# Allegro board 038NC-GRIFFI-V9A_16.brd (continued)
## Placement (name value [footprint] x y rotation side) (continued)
NOREF#1212  -  []  36 240.62 90 top
NOREF#1213  -  []  238.35 207.84 315 top
NOREF#1214  -  []  147.36 268.69 0 top
NOREF#1215  -  []  87.32 457.2 0 top
NOREF#1216  -  []  199.67 181.33 90 top
NOREF#1217  -  []  60.19 265.47 90 top
NOREF#1218  -  []  74.99 283.99 0 top
NOREF#1219  -  []  136.47 229.18 90 top
NOREF#1220  -  []  196.47 301.68 90 top
NOREF#1221  -  []  225.06 203.86 0 top
NOREF#1222  -  []  60.84 300.88 90 top
NOREF#1223  -  []  115.97 164.05 90 top
NOREF#1224  -  []  224.98 281.49 90 top
NOREF#1225  -  []  105.92 225.18 90 top
NOREF#1226  -  []  175.7 198.99 90 top
NOREF#1227  -  []  43.9 20.69 90 top
NOREF#1228  -  []  91.47 105.11 90 top
NOREF#1229  -  []  134.98 193.49 90 top
NOREF#1230  -  []  207.95 83.81 0 top
NOREF#1231  -  []  30.19 205.47 90 top
NOREF#1232  -  []  78.48 174.1 0 top
NOREF#1233  -  []  104.99 281.49 90 top
NOREF#1234  -  []  16.47 301.68 0 top
NOREF#1235  -  []  44.4 120.65 0 top
NOREF#1236  -  []  153.41 234.38 0 top
NOREF#1237  -  []  113.38 284.14 90 top
NOREF#1238  -  []  58.45 115.65 90 top
NOREF#1239  -  []  75.92 300.88 90 top
NOREF#1240  -  []  98.86 233.58 0 top
NOREF#1241  -  []  232.98 226.49 0 top
NOREF#1242  -  []  158.86 139.12 90 top
NOREF#1243  -  []  194.3 17.15 90 top
NOREF#1244  -  []  82.73 114.89 0 top
NOREF#1245  -  []  60.19 205.86 90 top
NOREF#1246  -  []  27.13 170.1 90 top
NOREF#1247  -  []  226.47 304.88 90 top
NOREF#1248  -  []  177.17 105.04 0 top
NOREF#1249  -  []  45.06 269.26 90 top
NOREF#1250  -  []  143.93 290.34 90 top
NOREF#1251  -  []  83.93 231.38 90 top
NOREF#1252  -  []  31.01 206.29 90 top
NOREF#1253  -  []  136.47 225.98 90 top
NOREF#1254  -  []  160.89 283.29 90 top
NOREF#1255  -  []  22.99 286.49 0 top
NOREF#1256  -  []  64.59 287.14 90 top
NOREF#1257  -  []  55.97 179.68 90 top
NOREF#1258  -  []  172.98 188.49 90 top
NOREF#1259  -  []  135.92 284.14 90 top
NOREF#1260  -  []  31.01 206.69 90 top
NOREF#1261  -  []  154.59 230.38 90 top
NOREF#1262  -  []  124.59 230.38 90 top
NOREF#1263  -  []  154.59 289.34 90 top
NOREF#1264  -  []  139.67 183.53 90 top
NOREF#1265  -  []  91.4 292.54 0 top
NOREF#1266  -  []  106.47 249.87 0 top
NOREF#1267  -  []  57.13 303.88 90 top
NOREF#1268  -  []  98.86 142.32 90 top
NOREF#1269  -  []  91.4 307.08 90 top
NOREF#1270  -  []  98.86 301.68 90 top
NOREF#1271  -  []  22.99 248.49 0 top
NOREF#1272  -  []  244.59 225.98 90 top
NOREF#1273  -  []  104.99 193.49 90 top
NOREF#1274  -  []  137.98 278.49 0 top
NOREF#1275  -  []  221.4 296.54 90 top
NOREF#1276  -  []  75.06 209.26 90 top
NOREF#1277  -  []  28.78 456.29 0 top
NOREF#1278  -  []  222.48 284.14 0 top
NOREF#1279  -  []  166.47 301.68 90 top
NOREF#1280  -  []  35.02 225.18 0 top
NOREF#1281  -  []  63.41 293.34 0 top
NOREF#1282  -  []  30 300.03 0 top
NOREF#1283  -  []  60.34 266.14 90 top
NOREF#1284  -  []  134.98 283.99 0 top
NOREF#1285  -  []  162.06 244.47 90 top
NOREF#1286  -  []  211.39 168.9 90 top
NOREF#1287  -  []  236.96 268.69 0 top
NOREF#1288  -  []  94.59 287.14 90 top
NOREF#1289  -  []  31.4 307.08 90 top
NOREF#1290  -  []  37.36 333.84 90 top
NOREF#1291  -  []  184.59 287.14 90 top
NOREF#1292  -  []  15.07 300.03 0 top
NOREF#1293  -  []  68.31 300.88 90 top
NOREF#1294  -  []  94.59 289.34 90 top
NOREF#1295  -  []  57.36 208.69 0 top
NOREF#1296  -  []  218.86 139.12 0 top
NOREF#1297  -  []  117.79 269.51 0 top
NOREF#1298  -  []  48.48 174.1 0 top
NOREF#1299  -  []  235.94 234.38 0 top
NOREF#1300  -  []  130.18 389.27 90 top
NOREF#1301  -  []  198.48 250.67 0 top
NOREF#1302  -  []  149.43 456.29 0 top
NOREF#1303  -  []  117.13 185.73 90 top
NOREF#1304  -  []  90.34 266.14 90 top
NOREF#1305  -  []  207.13 246.67 90 top
NOREF#1306  -  []  44.99 223.99 0 top
NOREF#1307  -  []  131.02 174.1 0 top
NOREF#1308  -  []  44.99 253.49 90 top
NOREF#1309  -  []  187.55 263.78 0 top
NOREF#1310  -  []  177.13 303.88 90 top
NOREF#1311  -  []  124.59 228.18 90 top
NOREF#1312  -  []  71.82 117.35 90 top
NOREF#1313  -  []  172.98 248.49 0 top
NOREF#1314  -  []  163.73 103.85 90 top
NOREF#1315  -  []  132.06 165.7 90 top
NOREF#1316  -  []  237.13 244.47 90 top
NOREF#1317  -  []  74.99 250.99 90 top
NOREF#1318  -  []  190.89 237.58 90 top
NOREF#1319  -  []  164.56 456.29 90 top
NOREF#1320  -  []  42.06 228.18 90 top
NOREF#1321  -  []  193.01 240.57 90 top
NOREF#1322  -  []  81.92 389.27 90 top
NOREF#1323  -  []  59.02 105.89 90 top
NOREF#1324  -  []  65.02 225.18 0 top
NOREF#1325  -  []  14.99 221.49 90 top
NOREF#1326  -  []  27.13 244.47 90 top
NOREF#1327  -  []  210.67 176.51 90 top
NOREF#1328  -  []  52.99 226.49 0 top
NOREF#1329  -  []  71.03 112.93 0 top
NOREF#1330  -  []  179.38 269.51 0 top
NOREF#1331  -  []  170.17 17.15 0 top
NOREF#1332  -  []  44.99 193.49 90 top
NOREF#1333  -  []  188.86 307.08 90 top
NOREF#1334  -  []  60.84 164.9 90 top
NOREF#1335  -  []  47.99 256.49 90 top
NOREF#1336  -  []  76.47 304.88 90 top
NOREF#1337  -  []  213.41 250.67 0 top
NOREF#1338  -  []  158.39 253.49 45 top
NOREF#1339  -  []  108.48 174.1 0 top
NOREF#1340  -  []  221.02 174.1 0 top
NOREF#1341  -  []  195.92 225.18 90 top
NOREF#1342  -  []  101.02 189.73 0 top
NOREF#1343  -  []  41.02 189.73 0 top
NOREF#1344  -  []  248.86 173.3 0 top
NOREF#1345  -  []  57.82 107.19 0 top
NOREF#1346  -  []  92.32 110.11 0 top
NOREF#1347  -  []  161.02 174.1 0 top
NOREF#1348  -  []  214.59 183.53 90 top
NOREF#1349  -  []  98.86 292.54 0 top
NOREF#1350  -  []  20.74 275.74 0 top
NOREF#1351  -  []  218.86 307.08 90 top
NOREF#1352  -  []  134.98 281.49 90 top
NOREF#1353  -  []  42.61 174.1 0 top
NOREF#1354  -  []  173.66 106.41 90 top
NOREF#1355  -  []  183.43 240.62 90 top
NOREF#1356  -  []  147.63 208.84 0 top
NOREF#1357  -  []  207.63 268.84 0 top
NOREF#1358  -  []  132.06 185.73 90 top
NOREF#1359  -  []  226.47 284.94 90 top
NOREF#1360  -  []  194.98 221.49 90 top
NOREF#1361  -  []  14.22 225.18 90 top
NOREF#1362  -  []  102.48 225.18 0 top
NOREF#1363  -  []  177.79 269.51 0 top
NOREF#1364  -  []  209.32 268.11 315 top
NOREF#1365  -  []  187.23 259.24 90 top
NOREF#1366  -  []  188.86 139.12 90 top
NOREF#1367  -  []  49.67 244.47 90 top
NOREF#1368  -  []  46.47 301.68 0 top
NOREF#1369  -  []  37.46 300.03 90 top
NOREF#1370  -  []  173.93 231.38 90 top
NOREF#1371  -  []  55.7 258.99 90 top
NOREF#1372  -  []  177.13 242.27 90 top
NOREF#1373  -  []  100.89 240.62 90 top
NOREF#1374  -  []  53.93 229.18 90 top
NOREF#1375  -  []  87.64 268.84 0 top
NOREF#1376  -  []  43.81 238.87 0 top
NOREF#1377  -  []  113.93 173.3 0 top
NOREF#1378  -  []  121.39 249.87 0 top
NOREF#1379  -  []  37.46 251.52 0 top
NOREF#1380  -  []  133.3 120.65 0 top
NOREF#1381  -  []  31.4 292.54 0 top
NOREF#1382  -  []  94.59 230.38 90 top
NOREF#1383  -  []  202.98 248.49 90 top
NOREF#1384  -  []  124.59 284.94 90 top
NOREF#1385  -  []  208.35 207.84 315 top
NOREF#1386  -  []  151.39 233.58 0 top
NOREF#1387  -  []  57.79 209.51 0 top
NOREF#1388  -  []  235.7 198.99 90 top
NOREF#1389  -  []  64.59 228.18 90 top
NOREF#1390  -  []  46.47 304.88 90 top
NOREF#1391  -  []  57.13 306.08 90 top
NOREF#1392  -  []  132.48 225.18 0 top
NOREF#1393  -  []  157.55 263.78 0 top
NOREF#1394  -  []  91.4 165.7 90 top
NOREF#1395  -  []  34.6 225.98 90 top
NOREF#1396  -  []  116.96 208.69 0 top
NOREF#1397  -  []  42.48 225.18 0 top
NOREF#1398  -  []  74.99 281.49 90 top
NOREF#1399  -  []  83.93 188.93 0 top
NOREF#1400  -  []  78.48 189.73 0 top
NOREF#1401  -  []  33.99 389.27 90 top
NOREF#1402  -  []  227.03 389.27 90 top
NOREF#1403  -  []  19.78 456.29 0 top
NOREF#1404  -  []  79.67 167.9 90 top
NOREF#1405  -  []  190.78 112.83 0 top
NOREF#1406  -  []  161.02 189.73 0 top
NOREF#1407  -  []  100.89 224.33 90 top
NOREF#1408  -  []  23.93 229.18 90 top
NOREF#1409  -  []  22.99 188.49 0 top
NOREF#1410  -  []  190.47 111.76 90 top
NOREF#1411  -  []  128.86 142.32 90 top
NOREF#1412  -  []  135.56 82.55 0 top
NOREF#1413  -  []  203.93 284.94 90 top
NOREF#1414  -  []  85.97 164.05 90 top
NOREF#1415  -  []  3.61 203.06 0 top
NOREF#1416  -  []  91.47 115.65 90 top
NOREF#1417  -  []  233.38 284.14 90 top
NOREF#1418  -  []  102.06 244.47 90 top
NOREF#1419  -  []  99.47 115.65 0 top
NOREF#1420  -  []  243.41 189.73 0 top
NOREF#1421  -  []  243.56 82.65 0 top
NOREF#1422  -  []  145.7 198.99 90 top
NOREF#1423  -  []  107.21 143.34 90 top
NOREF#1424  -  []  37.55 263.78 0 top
NOREF#1425  -  []  117.13 246.67 90 top
NOREF#1426  -  []  203.93 309.28 0 top
NOREF#1427  -  []  138.36 240.62 90 top
NOREF#1428  -  []  229.67 170.1 90 top
NOREF#1429  -  []  173.93 249.87 0 top
NOREF#1430  -  []  135.92 300.88 90 top
NOREF#1431  -  []  17.53 452.29 90 top
NOREF#1432  -  []  178.37 267.15 315 top
NOREF#1433  -  []  55.7 198.99 90 top
NOREF#1434  -  []  93.43 300.03 90 top
NOREF#1435  -  []  230.48 210.77 0 top
NOREF#1436  -  []  104.99 223.99 0 top
NOREF#1437  -  []  192.06 287.14 90 top
NOREF#1438  -  []  258.36 179.68 90 top
NOREF#1439  -  []  199.93 18.69 90 top
NOREF#1440  -  []  108.48 189.73 0 top
NOREF#1441  -  []  36 283.29 90 top
NOREF#1442  -  []  101.4 296.54 90 top
NOREF#1443  -  []  207.36 268.69 0 top
NOREF#1444  -  []  169.67 332.66 90 top
NOREF#1445  -  []  211.39 301.68 0 top
NOREF#1446  -  []  130.89 283.29 90 top
NOREF#1447  -  []  87.36 208.69 0 top
NOREF#1448  -  []  86.96 268.69 0 top
NOREF#1449  -  []  221.02 189.73 0 top
NOREF#1450  -  []  244.59 230.38 90 top
NOREF#1451  -  []  151.39 168.9 90 top
NOREF#1452  -  []  28.37 207.15 315 top
NOREF#1453  -  []  45.92 300.88 90 top
NOREF#1454  -  []  149.39 269.51 0 top
NOREF#1455  -  []  143.93 249.87 0 top
NOREF#1456  -  []  227.98 196.49 90 top
NOREF#1457  -  []  188.69 396.29 0 top
NOREF#1458  -  []  31.02 18.69 90 top
NOREF#1459  -  []  121.91 17.2 0 top
NOREF#1460  -  []  196.47 231.38 90 top
NOREF#1461  -  []  70.89 283.29 90 top
NOREF#1462  -  []  52.99 248.49 0 top
NOREF#1463  -  []  57.13 183.53 90 top
NOREF#1464  -  []  136.47 284.94 90 top
NOREF#1465  -  []  211.39 233.58 0 top
NOREF#1466  -  []  38.66 177.76 90 top
NOREF#1467  -  []  194.98 223.99 0 top
NOREF#1468  -  []  138.36 164.05 90 top
NOREF#1469  -  []  124.59 225.98 90 top
NOREF#1470  -  []  106.47 284.94 0 top
NOREF#1471  -  []  181.39 304.88 90 top
NOREF#1472  -  []  191.4 296.54 90 top
NOREF#1473  -  []  157.36 333.84 90 top
NOREF#1474  -  []  117.13 244.47 90 top
NOREF#1475  -  []  173.93 284.94 0 top
NOREF#1476  -  []  154.59 246.67 90 top
NOREF#1477  -  []  169.67 181.33 90 top
NOREF#1478  -  []  227.21 143.34 90 top
NOREF#1479  -  []  14.99 250.99 90 top
NOREF#1480  -  []  94.22 115.65 0 top
NOREF#1481  -  []  117.13 183.53 90 top
NOREF#1482  -  []  136.47 284.94 0 top
NOREF#1483  -  []  157.55 203.78 0 top
NOREF#1484  -  []  230.73 215.74 0 top
NOREF#1485  -  []  22.53 283.29 0 top
NOREF#1486  -  []  205.7 198.99 90 top
NOREF#1487  -  []  27.13 165.7 90 top
NOREF#1488  -  []  44.99 281.49 90 top
NOREF#1489  -  []  61.01 206.69 90 top
NOREF#1490  -  []  89.39 269.51 0 top
NOREF#1491  -  []  188.86 173.3 0 top
NOREF#1492  -  []  120.34 266.14 90 top
NOREF#1493  -  []  213.41 234.38 0 top
NOREF#1494  -  []  127.41 115.65 0 top
NOREF#1495  -  []  23.93 225.98 90 top
NOREF#1496  -  []  63.43 240.62 90 top
NOREF#1497  -  []  83.93 225.98 0 top
NOREF#1498  -  []  14.99 190.99 90 top
NOREF#1499  -  []  115.7 198.99 90 top
NOREF#1500  -  []  46.47 225.98 0 top
NOREF#1501  -  []  210.33 206.14 90 top
NOREF#1502  -  []  228.48 310.08 0 top
NOREF#1503  -  []  230.48 270.77 0 top
NOREF#1504  -  []  43.88 117.35 90 top
NOREF#1505  -  []  89.32 208.11 315 top
NOREF#1506  -  []  140.43 456.29 0 top
NOREF#1507  -  []  27.13 167.9 90 top
NOREF#1508  -  []  196.47 229.18 90 top
NOREF#1509  -  []  115.97 326.61 90 top
NOREF#1510  -  []  248.86 301.68 90 top
NOREF#1511  -  []  207.13 301.68 90 top
NOREF#1512  -  []  211.68 19.69 90 top
NOREF#1513  -  []  219.43 82.65 0 top
NOREF#1514  -  []  29.32 268.11 315 top
NOREF#1515  -  []  150.18 265.47 90 top
NOREF#1516  -  []  23.93 231.38 90 top
NOREF#1517  -  []  222.06 284.94 90 top
NOREF#1518  -  []  177.13 246.67 90 top
NOREF#1519  -  []  224.98 190.99 90 top
NOREF#1520  -  []  252.06 246.67 90 top
NOREF#1521  -  []  177.41 138.32 0 top
NOREF#1522  -  []  218.86 301.68 90 top
NOREF#1523  -  []  59.02 106.54 90 top
NOREF#1524  -  []  43.88 106.81 0 top
NOREF#1525  -  []  97.36 333.84 90 top
NOREF#1526  -  []  44.99 221.49 90 top
NOREF#1527  -  []  198.48 189.73 0 top
NOREF#1528  -  []  92.16 18.69 0 top
NOREF#1529  -  []  158.86 173.3 0 top
NOREF#1530  -  []  191.02 189.73 0 top
NOREF#1531  -  []  222.48 225.18 0 top
NOREF#1532  -  []  30.19 265.86 90 top
NOREF#1533  -  []  242.56 17.15 90 top
NOREF#1534  -  []  217.23 259.24 90 top
NOREF#1535  -  []  106.47 225.98 90 top
NOREF#1536  -  []  147.13 306.08 90 top
NOREF#1537  -  []  243.43 240.62 90 top
NOREF#1538  -  []  136.47 307.08 90 top
NOREF#1539  -  []  30 294.19 0 top
NOREF#1540  -  []  15.07 300.03 90 top
NOREF#1541  -  []  122.91 82.65 0 top
NOREF#1542  -  []  104.99 190.99 90 top
NOREF#1543  -  []  113.93 229.18 90 top
NOREF#1544  -  []  91.4 165.7 0 top
NOREF#1545  -  []  154.59 185.73 90 top
NOREF#1546  -  []  218.86 233.58 0 top
NOREF#1547  -  []  16.47 307.08 90 top
NOREF#1548  -  []  215.02 284.14 0 top
NOREF#1549  -  []  142.98 226.49 0 top
NOREF#1550  -  []  198.48 310.08 0 top
NOREF#1551  -  []  233.93 288.14 90 top
NOREF#1552  -  []  241.01 206.69 90 top
NOREF#1553  -  []  68.86 144.52 90 top
NOREF#1554  -  []  145.94 250.67 0 top
NOREF#1555  -  []  238.65 206.87 45 top
NOREF#1556  -  []  102.06 284.94 90 top
NOREF#1557  -  []  59.32 268.11 315 top
NOREF#1558  -  []  206.96 268.69 0 top
NOREF#1559  -  []  162.06 181.33 90 top
NOREF#1560  -  []  42.06 244.47 90 top
NOREF#1561  -  []  213.41 189.73 0 top
NOREF#1562  -  []  211.39 301.68 90 top
NOREF#1563  -  []  169.67 183.53 90 top
NOREF#1564  -  []  127.55 454.29 90 top
NOREF#1565  -  []  225.92 300.88 90 top
NOREF#1566  -  []  38.86 307.08 90 top
NOREF#1567  -  []  124.59 287.14 90 top
NOREF#1568  -  []  74.99 221.49 90 top
NOREF#1569  -  []  46.47 173.3 0 top
NOREF#1570  -  []  61.01 266.69 90 top
NOREF#1571  -  []  113.93 188.93 0 top
NOREF#1572  -  []  57.41 138.32 0 top
NOREF#1573  -  []  145.97 179.68 90 top
NOREF#1574  -  []  85.97 179.68 90 top
NOREF#1575  -  []  180.33 206.14 90 top
NOREF#1576  -  []  20.49 210.77 0 top
NOREF#1577  -  []  27.36 268.69 0 top
NOREF#1578  -  []  207.13 306.08 90 top
NOREF#1579  -  []  188.86 139.12 0 top
NOREF#1580  -  []  55.97 164.05 90 top
NOREF#1581  -  []  211.39 304.88 90 top
NOREF#1582  -  []  250.89 179.68 90 top
NOREF#1583  -  []  166.47 249.87 0 top
NOREF#1584  -  []  208.37 207.15 315 top
NOREF#1585  -  []  95.02 284.14 0 top
NOREF#1586  -  []  100.9 237.58 90 top
NOREF#1587  -  []  162.06 246.67 90 top
NOREF#1588  -  []  58.37 207.15 315 top
NOREF#1589  -  []  26.96 208.69 0 top
NOREF#1590  -  []  121.39 292.54 0 top
NOREF#1591  -  []  211.01 206.29 90 top
NOREF#1592  -  []  67.24 199.24 90 top
NOREF#1593  -  []  253.01 240.57 90 top
NOREF#1594  -  []  33.43 179.68 90 top
NOREF#1595  -  []  79.29 454.29 90 top
NOREF#1596  -  []  15.06 203.86 90 top
NOREF#1597  -  []  211.01 206.69 90 top
NOREF#1598  -  []  130.89 240.62 90 top
NOREF#1599  -  []  57.36 268.69 0 top
NOREF#1600  -  []  74.99 193.49 90 top
NOREF#1601  -  []  77.99 218.49 0 top
NOREF#1602  -  []  123.43 179.68 90 top
NOREF#1603  -  []  74.99 221.49 90 top
NOREF#1604  -  []  158.31 300.88 90 top
NOREF#1605  -  []  224.98 283.99 0 top
NOREF#1606  -  []  39.06 458.49 0 top
NOREF#1607  -  []  180.84 164.9 90 top
NOREF#1608  -  []  139.67 332.66 90 top
NOREF#1609  -  []  87.13 181.33 90 top
NOREF#1610  -  []  130.9 239.1 90 top
NOREF#1611  -  []  55.97 240.62 90 top
NOREF#1612  -  []  136.47 335.86 0 top
NOREF#1613  -  []  48.48 250.67 0 top
NOREF#1614  -  []  239.38 269.51 0 top
NOREF#1615  -  []  178.65 266.87 45 top
NOREF#1616  -  []  63.61 203.06 0 top
NOREF#1617  -  []  16.47 225.98 0 top
NOREF#1618  -  []  151.39 188.93 0 top
NOREF#1619  -  []  72.06 287.14 90 top
NOREF#1620  -  []  178.35 207.84 315 top
NOREF#1621  -  []  125.02 300.88 0 top
NOREF#1622  -  []  38.86 139.12 0 top
NOREF#1623  -  []  50.52 82.65 0 top
NOREF#1624  -  []  154.59 287.14 90 top
NOREF#1625  -  []  61.01 206.29 90 top
NOREF#1626  -  []  97.24 199.24 90 top
NOREF#1627  -  []  237.41 138.32 0 top
NOREF#1628  -  []  16.47 225.98 90 top
NOREF#1629  -  []  89.29 207.51 45 top
NOREF#1630  -  []  190.78 112.83 90 top
NOREF#1631  -  []  49.67 165.7 90 top
NOREF#1632  -  []  37.55 203.78 0 top
NOREF#1633  -  []  38.51 115.65 0 top
NOREF#1634  -  []  146.03 119.76 0 top
NOREF#1635  -  []  106.47 301.68 90 top
NOREF#1636  -  []  240.65 236.45 90 top
NOREF#1637  -  []  237.13 185.73 90 top
NOREF#1638  -  []  117.13 181.33 90 top
NOREF#1639  -  []  59.02 107.84 90 top
NOREF#1640  -  []  148.35 267.84 315 top
NOREF#1641  -  []  238.35 207.84 45 top
NOREF#1642  -  []  233.38 225.18 90 top
NOREF#1643  -  []  151.39 307.08 90 top
NOREF#1644  -  []  53.93 225.98 90 top
NOREF#1645  -  []  210.18 205.47 90 top
NOREF#1646  -  []  195.92 300.88 90 top
NOREF#1647  -  []  243.41 234.38 0 top
NOREF#1648  -  []  192.48 225.18 0 top
NOREF#1649  -  []  236.95 456.29 0 top
NOREF#1650  -  []  187.23 199.24 90 top
NOREF#1651  -  []  136.47 301.68 0 top
NOREF#1652  -  []  214.59 287.14 90 top
NOREF#1653  -  []  146.96 208.69 0 top
NOREF#1654  -  []  199.67 183.53 90 top
NOREF#1655  -  []  128.73 111.38 90 top
NOREF#1656  -  []  150.18 265.86 90 top
NOREF#1657  -  []  205.97 164.05 90 top
NOREF#1658  -  []  88.35 267.84 45 top
NOREF#1659  -  []  145.94 234.38 0 top
NOREF#1660  -  []  181.01 206.69 90 top
NOREF#1661  -  []  94.59 284.94 90 top
NOREF#1662  -  []  49.67 181.33 90 top
NOREF#1663  -  []  244.59 284.94 90 top
NOREF#1664  -  []  53.93 284.94 0 top
NOREF#1665  -  []  240.18 205.86 90 top
NOREF#1666  -  []  90.65 236.45 90 top
NOREF#1667  -  []  205.97 326.61 90 top
NOREF#1668  -  []  61.4 304.88 90 top
NOREF#1669  -  []  123.41 293.34 0 top
NOREF#1670  -  []  130.9 237.58 90 top
NOREF#1671  -  []  224.98 253.49 90 top
NOREF#1672  -  []  91.4 304.88 90 top
NOREF#1673  -  []  135.06 267.06 90 top
NOREF#1674  -  []  74.99 223.99 0 top
NOREF#1675  -  []  44.99 190.99 90 top
NOREF#1676  -  []  38.86 139.12 90 top
NOREF#1677  -  []  146.04 17.15 0 top
NOREF#1678  -  []  198.48 174.1 0 top
NOREF#1679  -  []  199.67 242.27 90 top
NOREF#1680  -  []  14.99 281.49 90 top
NOREF#1681  -  []  105.06 263.86 90 top
NOREF#1682  -  []  230.73 275.74 0 top
NOREF#1683  -  []  207.13 167.9 90 top
NOREF#1684  -  []  194.98 221.49 90 top
NOREF#1685  -  []  42.06 242.27 90 top
NOREF#1686  -  []  241.01 266.69 90 top
NOREF#1687  -  []  98.86 307.08 90 top
NOREF#1688  -  []  37.46 294.19 0 top
NOREF#1689  -  []  169.94 300.88 0 top
NOREF#1690  -  []  67.36 333.84 90 top
NOREF#1691  -  []  147.79 269.51 0 top
NOREF#1692  -  []  115.97 240.62 90 top
NOREF#1693  -  []  243.41 250.67 0 top
NOREF#1694  -  []  128.86 173.3 0 top
NOREF#1695  -  []  42.61 234.38 0 top
NOREF#1696  -  []  98.86 139.12 0 top
NOREF#1697  -  []  252.06 228.18 90 top
NOREF#1698  -  []  34.6 289.34 90 top
NOREF#1699  -  []  169.94 164.9 0 top
NOREF#1700  -  []  38.39 253.49 45 top
NOREF#1701  -  []  87.79 269.51 0 top
NOREF#1702  -  []  177.79 209.51 0 top
NOREF#1703  -  []  179.38 209.51 0 top
NOREF#1704  -  []  237.13 306.08 90 top
NOREF#1705  -  []  229.67 165.7 90 top
NOREF#1706  -  []  81.68 112.1 0 top
NOREF#1707  -  []  252.06 181.33 90 top
NOREF#1708  -  []  102.06 246.67 90 top
NOREF#1709  -  []  154.31 14.59 90 top
NOREF#1710  -  []  252.06 185.73 90 top
NOREF#1711  -  []  130.49 14.59 90 top
NOREF#1712  -  []  58.65 266.87 45 top
NOREF#1713  -  []  169.67 185.73 90 top
NOREF#1714  -  []  45.06 263.86 90 top
NOREF#1715  -  []  164.98 281.49 90 top
NOREF#1716  -  []  147.13 170.1 90 top
NOREF#1717  -  []  112.99 248.49 0 top
NOREF#1718  -  []  78.36 179.68 90 top
NOREF#1719  -  []  170.48 270.77 0 top
NOREF#1720  -  []  196.47 307.08 90 top
NOREF#1721  -  []  105.36 120.65 0 top
NOREF#1722  -  []  14.99 193.49 90 top
NOREF#1723  -  []  78.36 240.62 90 top
NOREF#1724  -  []  76.47 284.94 0 top
NOREF#1725  -  []  85.7 198.99 90 top
NOREF#1726  -  []  97.78 17.2 90 top
NOREF#1727  -  []  188.86 233.58 0 top
NOREF#1728  -  []  94.59 244.47 90 top
NOREF#1729  -  []  161.4 298.06 90 top
NOREF#1730  -  []  38.86 144.52 90 top
NOREF#1731  -  []  16.47 301.68 90 top
NOREF#1732  -  []  142.98 248.49 0 top
NOREF#1733  -  []  125.3 456.29 0 top
NOREF#1734  -  []  188.86 144.52 90 top
NOREF#1735  -  []  178.44 389.27 90 top
NOREF#1736  -  []  81.95 109.2 90 top
NOREF#1737  -  []  68.86 307.08 90 top
NOREF#1738  -  []  14.22 225.18 0 top
NOREF#1739  -  []  88.37 207.15 315 top
NOREF#1740  -  []  150.65 236.45 90 top
NOREF#1741  -  []  164.98 193.49 90 top
NOREF#1742  -  []  134.98 221.49 90 top
NOREF#1743  -  []  220.89 179.68 90 top
NOREF#1744  -  []  52.99 188.49 0 top
NOREF#1745  -  []  224.98 221.49 90 top
NOREF#1746  -  []  115.88 237.76 90 top
NOREF#1747  -  []  19.67 165.7 90 top
NOREF#1748  -  []  112.99 226.49 0 top
NOREF#1749  -  []  72.06 230.38 90 top
NOREF#1750  -  []  237.41 300.88 0 top
NOREF#1751  -  []  202.98 248.49 0 top
NOREF#1752  -  []  78.48 310.08 0 top
NOREF#1753  -  []  218.39 193.49 45 top
NOREF#1754  -  []  136.47 231.38 90 top
NOREF#1755  -  []  30 300.03 90 top
NOREF#1756  -  []  226.47 173.3 0 top
NOREF#1757  -  []  53.93 249.87 0 top
NOREF#1758  -  []  209.29 207.51 45 top
NOREF#1759  -  []  53.93 309.28 0 top
NOREF#1760  -  []  203.38 225.18 90 top
NOREF#1761  -  []  149.29 207.51 45 top
NOREF#1762  -  []  31.4 188.93 0 top
NOREF#1763  -  []  212.82 456.29 90 top
NOREF#1764  -  []  23.93 309.28 0 top
NOREF#1765  -  []  168.48 174.1 0 top
NOREF#1766  -  []  229.67 181.33 90 top
NOREF#1767  -  []  135.06 263.86 90 top
NOREF#1768  -  []  45.06 203.86 0 top
NOREF#1769  -  []  21.07 326.61 90 top
NOREF#1770  -  []  199.67 165.7 90 top
NOREF#1771  -  []  132.06 228.18 90 top
NOREF#1772  -  []  53.93 288.14 90 top
NOREF#1773  -  []  162.06 242.27 90 top
NOREF#1774  -  []  101.4 298.06 90 top
NOREF#1775  -  []  128.86 249.87 0 top
NOREF#1776  -  []  73.01 240.57 90 top
NOREF#1777  -  []  162.06 165.7 90 top
NOREF#1778  -  []  198.36 179.68 90 top
NOREF#1779  -  []  179.29 267.51 45 top
NOREF#1780  -  []  205.94 293.34 0 top
NOREF#1781  -  []  87.41 300.88 0 top
NOREF#1782  -  []  46.47 229.18 90 top
NOREF#1783  -  []  59.3 120.65 0 top
NOREF#1784  -  []  63.41 189.73 0 top
NOREF#1785  -  []  236.94 18.69 0 top
NOREF#1786  -  []  57.13 167.9 90 top
NOREF#1787  -  []  183.61 263.06 0 top
NOREF#1788  -  []  76.47 301.68 90 top
NOREF#1789  -  []  248.39 193.49 45 top
NOREF#1790  -  []  52.99 188.49 90 top
NOREF#1791  -  []  199.67 167.9 90 top
NOREF#1792  -  []  116.3 456.29 0 top
NOREF#1793  -  []  39.04 16.49 0 top
NOREF#1794  -  []  34.6 228.18 90 top
NOREF#1795  -  []  112.99 188.49 0 top
NOREF#1796  -  []  248.86 142.32 90 top
NOREF#1797  -  []  50.49 270.77 0 top
NOREF#1798  -  []  61.4 168.9 90 top
NOREF#1799  -  []  80.74 215.74 0 top
NOREF#1800  -  []  142.98 188.49 90 top
NOREF#1801  -  []  224.06 18.69 90 top
NOREF#1802  -  []  132.06 244.47 90 top
NOREF#1803  -  []  192.06 225.98 90 top
NOREF#1804  -  []  75.06 263.86 90 top
NOREF#1805  -  []  199.67 246.67 90 top
NOREF#1806  -  []  33.61 203.06 0 top
NOREF#1807  -  []  128.39 193.49 45 top
NOREF#1808  -  []  147.04 82.65 0 top
NOREF#1809  -  []  130.89 224.33 90 top
NOREF#1810  -  []  205.7 258.99 90 top
NOREF#1811  -  []  79.67 332.66 90 top
NOREF#1812  -  []  196.47 225.98 90 top
NOREF#1813  -  []  77.03 18.69 0 top
NOREF#1814  -  []  173.93 225.98 0 top
NOREF#1815  -  []  83.93 284.94 90 top
NOREF#1816  -  []  240.84 300.88 90 top
NOREF#1817  -  []  180.18 265.47 90 top
NOREF#1818  -  []  53.93 231.38 90 top
NOREF#1819  -  []  175.8 18.69 90 top
NOREF#1820  -  []  44.99 221.49 90 top
NOREF#1821  -  []  168.36 240.62 90 top
NOREF#1822  -  []  233.93 225.98 90 top
NOREF#1823  -  []  104.84 117.35 0 top
NOREF#1824  -  []  58.12 106.87 0 top
NOREF#1825  -  []  235.81 19.69 90 top
NOREF#1826  -  []  240.33 206.14 90 top
NOREF#1827  -  []  112.99 248.49 90 top
NOREF#1828  -  []  197.21 143.34 90 top
NOREF#1829  -  []  225.06 263.86 90 top
NOREF#1830  -  []  147.41 300.88 0 top
NOREF#1831  -  []  103.42 454.29 90 top
NOREF#1832  -  []  244.59 242.27 90 top
NOREF#1833  -  []  177.63 268.84 0 top
NOREF#1834  -  []  108.36 240.62 90 top
NOREF#1835  -  []  16.47 249.87 0 top
NOREF#1836  -  []  164.98 221.49 90 top
NOREF#1837  -  []  28.35 267.84 315 top
NOREF#1838  -  []  106.47 307.08 90 top
NOREF#1839  -  []  87.13 167.9 90 top
NOREF#1840  -  []  166.47 188.93 0 top
NOREF#1841  -  []  128.86 301.68 0 top
NOREF#1842  -  []  135.06 209.26 90 top
NOREF#1843  -  []  78.36 224.33 90 top
NOREF#1844  -  []  106.47 225.98 0 top
NOREF#1845  -  []  34.6 246.67 90 top
NOREF#1846  -  []  167.98 218.49 0 top
NOREF#1847  -  []  64.59 230.38 90 top
NOREF#1848  -  []  123.61 203.06 0 top
NOREF#1849  -  []  110.74 215.74 0 top
NOREF#1850  -  []  223.01 240.57 90 top
NOREF#1851  -  []  251.16 389.27 90 top
NOREF#1852  -  []  166.47 225.98 0 top
NOREF#1853  -  []  42.06 225.98 90 top
NOREF#1854  -  []  93.61 263.06 0 top
NOREF#1855  -  []  210.33 266.14 90 top
NOREF#1856  -  []  19.78 396.29 0 top
NOREF#1857  -  []  71.02 174.1 0 top
NOREF#1858  -  []  22.99 226.49 0 top
NOREF#1859  -  []  121.16 295.41 90 top
NOREF#1860  -  []  239.32 208.11 315 top
NOREF#1861  -  []  149.32 208.11 315 top
NOREF#1862  -  []  19.67 167.9 90 top
NOREF#1863  -  []  233.93 309.28 0 top
NOREF#1864  -  []  80.74 275.74 0 top
NOREF#1865  -  []  28.37 267.15 315 top
NOREF#1866  -  []  138.36 179.68 90 top
NOREF#1867  -  []  106.47 231.38 90 top
NOREF#1868  -  []  179.32 208.11 315 top
NOREF#1869  -  []  59.02 107.19 90 top
NOREF#1870  -  []  203.93 173.3 0 top
NOREF#1871  -  []  72.06 284.94 90 top
NOREF#1872  -  []  16.42 127.15 0 top
NOREF#1873  -  []  119.32 208.11 315 top
NOREF#1874  -  []  222.06 287.14 90 top
NOREF#1875  -  []  177.13 301.68 90 top
NOREF#1876  -  []  198.36 164.05 90 top
NOREF#1877  -  []  248.86 188.93 0 top
NOREF#1878  -  []  77.99 196.49 90 top
NOREF#1879  -  []  197.98 256.49 90 top
NOREF#1880  -  []  151.39 249.87 0 top
NOREF#1881  -  []  233.93 173.3 0 top
NOREF#1882  -  []  158.86 304.88 90 top
NOREF#1883  -  []  137.98 196.49 90 top
NOREF#1884  -  []  207.41 138.32 0 top
NOREF#1885  -  []  83.93 173.3 0 top
NOREF#1886  -  []  165.06 203.86 90 top
NOREF#1887  -  []  190.47 111.76 0 top
NOREF#1888  -  []  146.96 268.69 0 top
NOREF#1889  -  []  49.67 167.9 90 top
NOREF#1890  -  []  75.06 269.26 90 top
NOREF#1891  -  []  226.47 249.87 0 top
NOREF#1892  -  []  192.06 167.9 90 top
NOREF#1893  -  []  237.36 268.69 0 top
NOREF#1894  -  []  192.06 246.67 90 top
NOREF#1895  -  []  236.95 396.29 0 top
NOREF#1896  -  []  26.56 179.68 90 top
NOREF#1897  -  []  248.86 144.52 90 top
NOREF#1898  -  []  221.02 250.67 0 top
NOREF#1899  -  []  33.26 115.65 0 top
NOREF#1900  -  []  232.98 248.49 0 top
NOREF#1901  -  []  64.59 284.94 90 top
NOREF#1902  -  []  55.95 293.34 0 top
NOREF#1903  -  []  53.93 173.3 0 top
NOREF#1904  -  []  148.65 206.87 45 top
NOREF#1905  -  []  170.17 17.15 90 top
NOREF#1906  -  []  241.39 307.08 90 top
NOREF#1907  -  []  134.98 250.99 90 top
NOREF#1908  -  []  73.65 17.15 0 top
NOREF#1909  -  []  75.06 203.86 90 top
NOREF#1910  -  []  120.18 265.47 90 top
NOREF#1911  -  []  68.86 139.12 0 top
NOREF#1912  -  []  121.91 17.2 90 top
NOREF#1913  -  []  196.47 173.3 0 top
NOREF#1914  -  []  128.73 112.84 0 top
NOREF#1915  -  []  151.39 292.54 0 top
NOREF#1916  -  []  170.48 210.77 0 top
NOREF#1917  -  []  53.38 284.14 90 top
NOREF#1918  -  []  82.99 248.49 0 top
NOREF#1919  -  []  121.39 233.58 0 top
NOREF#1920  -  []  105.06 203.86 90 top
NOREF#1921  -  []  221.4 298.06 90 top
NOREF#1922  -  []  166.47 229.18 90 top
NOREF#1923  -  []  106.47 284.94 90 top
NOREF#1924  -  []  244.59 183.53 90 top
NOREF#1925  -  []  183.41 234.38 0 top
NOREF#1926  -  []  24.41 392.33 90 top
NOREF#1927  -  []  221.02 336.66 0 top
NOREF#1928  -  []  105.06 263.86 0 top
NOREF#1929  -  []  170.73 215.74 0 top
NOREF#1930  -  []  60.65 236.45 90 top
NOREF#1931  -  []  41.4 297.17 90 top
NOREF#1932  -  []  44.99 283.99 0 top
NOREF#1933  -  []  132.06 167.9 90 top
NOREF#1934  -  []  89.39 209.51 0 top
NOREF#1935  -  []  93.41 250.67 0 top
NOREF#1936  -  []  106.47 335.86 0 top
NOREF#1937  -  []  87.41 138.32 0 top
NOREF#1938  -  []  57.13 181.33 90 top
NOREF#1939  -  []  138.36 224.33 90 top
NOREF#1940  -  []  21.68 225.18 90 top
NOREF#1941  -  []  173.93 229.18 90 top
NOREF#1942  -  []  68.04 396.29 0 top
NOREF#1943  -  []  117.13 303.88 90 top
NOREF#1944  -  []  158.86 142.32 90 top
NOREF#1945  -  []  109.67 185.73 90 top
NOREF#1946  -  []  22.99 248.49 90 top
NOREF#1947  -  []  180.18 265.86 90 top
NOREF#1948  -  []  79.94 164.9 0 top
NOREF#1949  -  []  31.4 249.87 0 top
NOREF#1950  -  []  128.86 188.93 0 top
NOREF#1951  -  []  211.39 165.7 0 top
NOREF#1952  -  []  218.31 300.88 90 top
NOREF#1953  -  []  46.47 225.98 90 top
NOREF#1954  -  []  166.47 301.68 0 top
NOREF#1955  -  []  61.4 301.68 0 top
NOREF#1956  -  []  57.13 170.1 90 top
NOREF#1957  -  []  213.43 179.68 90 top
NOREF#1958  -  []  49.52 17.15 0 top
NOREF#1959  -  []  140.74 215.74 0 top
NOREF#1960  -  []  119.32 268.11 315 top
NOREF#1961  -  []  213.43 300.03 90 top
NOREF#1962  -  []  28.35 267.84 45 top
NOREF#1963  -  []  162.48 284.14 0 top
NOREF#1964  -  []  160.89 179.68 90 top
NOREF#1965  -  []  196.47 288.14 90 top
NOREF#1966  -  []  214.59 230.38 90 top
NOREF#1967  -  []  151.39 165.7 0 top
NOREF#1968  -  []  103.01 240.57 90 top
NOREF#1969  -  []  61.4 307.08 90 top
NOREF#1970  -  []  98.86 173.3 0 top
NOREF#1971  -  []  225.92 225.18 90 top
NOREF#1972  -  []  169.67 242.27 90 top
NOREF#1973  -  []  124.59 185.73 90 top
NOREF#1974  -  []  46.47 231.38 90 top
NOREF#1975  -  []  143.93 229.18 90 top
NOREF#1976  -  []  27.79 269.51 0 top
NOREF#1977  -  []  191.02 174.1 0 top
NOREF#1978  -  []  207.13 170.1 90 top
NOREF#1979  -  []  76.47 225.98 0 top
NOREF#1980  -  []  194.98 283.99 0 top
NOREF#1981  -  []  205.94 189.73 0 top
NOREF#1982  -  []  27.79 209.51 0 top
NOREF#1983  -  []  68.86 173.3 0 top
NOREF#1984  -  []  179.29 207.51 45 top
NOREF#1985  -  []  43.9 18.69 0 top
NOREF#1986  -  []  226.47 225.98 0 top
NOREF#1987  -  []  203.93 284.94 0 top
NOREF#1988  -  []  74.99 190.99 90 top
NOREF#1989  -  []  175.81 454.29 90 top
NOREF#1990  -  []  117.13 306.08 90 top
NOREF#1991  -  []  207.13 181.33 90 top
NOREF#1992  -  []  105.06 269.26 90 top
NOREF#1993  -  []  101.02 336.66 0 top
NOREF#1994  -  []  72.06 246.67 90 top
NOREF#1995  -  []  48.54 392.33 90 top
NOREF#1996  -  []  250.89 224.33 90 top
NOREF#1997  -  []  98.86 301.68 0 top
NOREF#1998  -  []  185.02 284.14 0 top
NOREF#1999  -  []  30 251.52 0 top
NOREF#2000  -  []  31.4 165.7 90 top
NOREF#2001  -  []  164.19 105.45 0 top
NOREF#2002  -  []  19.67 181.33 90 top
NOREF#2003  -  []  151.39 304.88 90 top
NOREF#2004  -  []  238.65 266.87 45 top
NOREF#2005  -  []  158.86 233.58 0 top
NOREF#2006  -  []  135.06 207.06 90 top
NOREF#2007  -  []  91.01 206.69 90 top
NOREF#2008  -  []  237.78 269.51 0 top
NOREF#2009  -  []  147.13 183.53 90 top
NOREF#2010  -  []  148.35 207.84 45 top
NOREF#2011  -  []  148.65 266.87 45 top
NOREF#2012  -  []  102.06 181.33 90 top
NOREF#2013  -  []  132.06 284.94 90 top
NOREF#2014  -  []  74.99 281.49 90 top
NOREF#2015  -  []  74.51 203.06 90 top
NOREF#2016  -  []  59.39 209.51 0 top
NOREF#2017  -  []  158.31 138.32 90 top
NOREF#2018  -  []  237.13 183.53 90 top
NOREF#2019  -  []  63.18 16.49 0 top
NOREF#2020  -  []  217.55 203.78 0 top
NOREF#2021  -  []  181.39 233.58 0 top
NOREF#2022  -  []  187.36 333.84 90 top
NOREF#2023  -  []  183.61 203.06 0 top
NOREF#2024  -  []  94.59 228.18 90 top
NOREF#2025  -  []  105.06 203.86 0 top
NOREF#2026  -  []  63.41 174.1 0 top
NOREF#2027  -  []  132.06 289.34 90 top
NOREF#2028  -  []  18.48 189.73 0 top
NOREF#2029  -  []  131.4 298.06 90 top
NOREF#2030  -  []  165.06 203.86 0 top
NOREF#2031  -  []  213.43 164.05 90 top
NOREF#2032  -  []  86.96 208.69 0 top
NOREF#2033  -  []  183.43 300.03 90 top
NOREF#2034  -  []  139.94 300.88 0 top
NOREF#2035  -  []  153.43 300.03 90 top
NOREF#2036  -  []  15.07 283.29 0 top
NOREF#2037  -  []  79.67 183.53 90 top
NOREF#2038  -  []  70.76 113.63 0 top
NOREF#2039  -  []  192.06 185.73 90 top
NOREF#2040  -  []  70.9 239.1 90 top
NOREF#2041  -  []  131.02 189.73 0 top
NOREF#2042  -  []  258.36 283.29 90 top
NOREF#2043  -  []  160.9 239.1 90 top
NOREF#2044  -  []  26.56 164.05 90 top
NOREF#2045  -  []  143.93 173.3 0 top
NOREF#2046  -  []  75.06 263.86 0 top
NOREF#2047  -  []  102.06 225.98 90 top
NOREF#2048  -  []  142.98 248.49 90 top
NOREF#2049  -  []  132.06 230.38 90 top
NOREF#2050  -  []  68.86 139.12 90 top
NOREF#2051  -  []  94.22 105.11 0 top
NOREF#2052  -  []  65.02 300.88 0 top
NOREF#2053  -  []  226.47 229.18 90 top
NOREF#2054  -  []  147.13 185.73 90 top
NOREF#2055  -  []  213.41 293.34 0 top
NOREF#2056  -  []  168.48 310.08 0 top
NOREF#2057  -  []  113.93 290.34 90 top
NOREF#2058  -  []  220.89 237.58 90 top
NOREF#2059  -  []  118.35 267.84 45 top
NOREF#2060  -  []  92.17 456.29 90 top
NOREF#2061  -  []  162.06 230.38 90 top
NOREF#2062  -  []  145.7 258.99 90 top
NOREF#2063  -  []  181.01 266.29 90 top
NOREF#2064  -  []  241.01 206.29 90 top
NOREF#2065  -  []  224.98 193.49 90 top
NOREF#2066  -  []  115.94 189.73 0 top
NOREF#2067  -  []  232.98 188.49 0 top
NOREF#2068  -  []  55.88 237.76 90 top
NOREF#2069  -  []  139.67 328.26 90 top
NOREF#2070  -  []  143.93 225.98 0 top
NOREF#2071  -  []  16.47 290.34 90 top
NOREF#2072  -  []  228.48 189.73 0 top
NOREF#2073  -  []  162.06 225.98 90 top
NOREF#2074  -  []  88.35 207.84 315 top
NOREF#2075  -  []  83.93 288.14 90 top
NOREF#2076  -  []  0 0 90 top
NOREF#2077  -  []  46.47 284.94 90 top
NOREF#2078  -  []  104.99 221.49 90 top
NOREF#2079  -  []  177.13 181.33 90 top
NOREF#2080  -  []  202.88 14.59 90 top
NOREF#2081  -  []  127.55 263.78 0 top
NOREF#2082  -  []  88.35 207.84 45 top
NOREF#2083  -  []  124.59 183.53 90 top
NOREF#2084  -  []  157.23 259.24 90 top
NOREF#2085  -  []  68.86 188.93 0 top
NOREF#2086  -  []  105.92 284.14 90 top
NOREF#2087  -  []  76.47 288.14 90 top
NOREF#2088  -  []  109.67 167.9 90 top
NOREF#2089  -  []  90.34 206.14 90 top
NOREF#2090  -  []  146.04 17.15 90 top
NOREF#2091  -  []  27.68 174.1 0 top
NOREF#2092  -  []  91.4 301.68 90 top
NOREF#2093  -  []  98.78 82.65 0 top
NOREF#2094  -  []  140.48 270.77 0 top
NOREF#2095  -  []  199.67 328.26 90 top
NOREF#2096  -  []  109.67 242.27 90 top
NOREF#2097  -  []  176.96 268.69 0 top
NOREF#2098  -  []  28.53 300.03 90 top
NOREF#2099  -  []  233.93 290.34 90 top
NOREF#2100  -  []  145.88 237.76 90 top
NOREF#2101  -  []  34.6 185.73 90 top
NOREF#2102  -  []  37.46 300.03 0 top
NOREF#2103  -  []  184.59 225.98 90 top
NOREF#2104  -  []  164.98 190.99 90 top
NOREF#2105  -  []  38.86 304.88 90 top
NOREF#2106  -  []  235.94 293.34 0 top
NOREF#2107  -  []  127.53 113.67 0 top
NOREF#2108  -  []  89.32 268.11 315 top
NOREF#2109  -  []  121.01 206.29 90 top
NOREF#2110  -  []  250.89 240.62 90 top
NOREF#2111  -  []  218.43 17.15 90 top
NOREF#2112  -  []  197.98 218.49 0 top
NOREF#2113  -  []  251.4 296.54 90 top
NOREF#2114  -  []  228.36 283.29 90 top
NOREF#2115  -  []  120.18 205.47 90 top
NOREF#2116  -  []  34.6 181.33 90 top
NOREF#2117  -  []  195.06 203.86 90 top
NOREF#2118  -  []  225.92 284.14 90 top
NOREF#2119  -  []  243.41 293.34 0 top
NOREF#2120  -  []  177.63 208.84 0 top
NOREF#2121  -  []  218.66 177.76 90 top
NOREF#2122  -  []  90.18 205.47 90 top
NOREF#2123  -  []  148.35 207.84 315 top
NOREF#2124  -  []  135.06 263.86 0 top
NOREF#2125  -  []  196.47 301.68 0 top
NOREF#2126  -  []  240.18 265.47 90 top
NOREF#2127  -  []  76.47 307.08 90 top
NOREF#2128  -  []  16.47 173.3 0 top
NOREF#2129  -  []  238.35 267.84 315 top
NOREF#2130  -  []  91.01 266.69 90 top
NOREF#2131  -  []  217.45 392.33 90 top
NOREF#2132  -  []  57.64 208.84 0 top
NOREF#2133  -  []  176.96 208.69 0 top
NOREF#2134  -  []  113.93 249.87 0 top
NOREF#2135  -  []  207.97 458.49 0 top
NOREF#2136  -  []  168.36 164.05 90 top
NOREF#2137  -  []  113.93 288.14 90 top
NOREF#2138  -  []  107.99 256.49 90 top
NOREF#2139  -  []  27.13 301.68 90 top
NOREF#2140  -  []  153.61 263.06 0 top
NOREF#2141  -  []  169.67 330.46 90 top
NOREF#2142  -  []  71.02 250.67 0 top
NOREF#2143  -  []  162.06 284.94 90 top
NOREF#2144  -  []  123.43 240.62 90 top
NOREF#2145  -  []  115.7 258.99 90 top
NOREF#2146  -  []  218.86 304.88 90 top
NOREF#2147  -  []  237.13 181.33 90 top
NOREF#2148  -  []  53.93 284.94 90 top
NOREF#2149  -  []  57.13 244.47 90 top
NOREF#2150  -  []  214.59 228.18 90 top
NOREF#2151  -  []  229.94 164.9 0 top
NOREF#2152  -  []  64.59 185.73 90 top
NOREF#2153  -  []  252.06 230.38 90 top
NOREF#2154  -  []  217.36 333.84 90 top
NOREF#2155  -  []  128.86 233.58 0 top
NOREF#2156  -  []  214.59 246.67 90 top
NOREF#2157  -  []  241.01 266.29 90 top
NOREF#2158  -  []  147.79 209.51 0 top
NOREF#2159  -  []  120.18 205.86 90 top
NOREF#2160  -  []  83.38 225.18 90 top
NOREF#2161  -  []  49.52 17.15 90 top
NOREF#2162  -  []  145.94 293.34 0 top
NOREF#2163  -  []  85.97 326.61 90 top
NOREF#2164  -  []  93.41 234.38 0 top
NOREF#2165  -  []  188.31 138.32 90 top
NOREF#2166  -  []  177.41 300.88 0 top
NOREF#2167  -  []  91.4 168.9 90 top
NOREF#2168  -  []  49.67 170.1 90 top
NOREF#2169  -  []  90.18 205.86 90 top
NOREF#2170  -  []  226.47 290.34 90 top
NOREF#2171  -  []  192.06 230.38 90 top
NOREF#2172  -  []  162.06 228.18 90 top
NOREF#2173  -  []  162.48 225.18 0 top
NOREF#2174  -  []  79.67 242.27 90 top
NOREF#2175  -  []  81.53 76.69 90 top
NOREF#2176  -  []  179.32 268.11 315 top
NOREF#2177  -  []  105.06 207.06 90 top
NOREF#2178  -  []  136.47 249.87 0 top
NOREF#2179  -  []  208.65 206.87 45 top
NOREF#2180  -  []  97.78 17.2 0 top
NOREF#2181  -  []  98.86 144.52 90 top
NOREF#2182  -  []  222.06 242.27 90 top
NOREF#2183  -  []  209.29 267.51 45 top
NOREF#2184  -  []  235.97 164.05 90 top
NOREF#2185  -  []  116.3 456.29 90 top
NOREF#2186  -  []  197.98 278.49 0 top
NOREF#2187  -  []  241.39 165.7 90 top
NOREF#2188  -  []  205.94 250.67 0 top
NOREF#2189  -  []  100.89 283.29 90 top
NOREF#2190  -  []  110.48 210.77 0 top
NOREF#2191  -  []  128.39 253.49 45 top
NOREF#2192  -  []  217.55 263.78 0 top
NOREF#2193  -  []  104.51 263.06 90 top
NOREF#2194  -  []  53.93 290.34 90 top
NOREF#2195  -  []  41.02 174.1 0 top
NOREF#2196  -  []  93.43 240.62 90 top
NOREF#2197  -  []  128.86 139.12 90 top
NOREF#2198  -  []  70.76 109.19 90 top
NOREF#2199  -  []  81.68 107.67 90 top
NOREF#2200  -  []  135.06 203.86 0 top
NOREF#2201  -  []  102.06 242.27 90 top
NOREF#2202  -  []  233.93 229.18 90 top
NOREF#2203  -  []  134.98 190.99 90 top
NOREF#2204  -  []  227.98 278.49 0 top
NOREF#2205  -  []  87.13 242.27 90 top
NPM1212-GRIFFI  REF-CODE-CHIP  [CHIP_CODE]  129.78 486.39 0 top
NPM1212-QFN28-P0.4  REF-CODE-CHIP  [CHIP_CODE]  130.39 486.39 0 top
R7  20K-1-S2  [R0201]  58.42 108.17 0 bottom
R8  20K-1-S2  [R0201]  58.42 107.52 0 bottom
R9  20K-1-S2  [R0201]  58.42 106.22 0 bottom
R10  20K-1-S2  [R0201]  58.42 106.87 0 bottom
R21  10K-1-S4  [R0402]  126.36 108.34 90 bottom
R22  0-1-S4-YA  [R0402]  125.14 112.15 270 bottom
R23  0-1-S4-YA  [R0402]  125.01 108.34 270 bottom
R24  0-1-S4-YA  [R0402]  125.86 110.11 180 bottom
R376  118-1-S2-YA  [R0201]  173.06 106.73 0 bottom
R378  365-1-S4  [R0402]  186.82 105.63 180 bottom
R381  750-1-S4  [R0402]  172.86 105.74 180 bottom
R382  75-1-S4  [R0402]  172.86 104.32 0 bottom
R383  121-1-S4  [R0402]  186.82 106.94 0 bottom
REG1_P3V3  TP01  [TP_040_T]  75.57 101.6 0 top
REG1_P_5V  TP01  [TP_040_T]  197.21 118.36 0 top
REG1_P_10V  TP01  [TP_040_T]  162.85 118.34 0 top
RLY_5V1  LDG-2-S8  [LED_0805]  27.31 126.05 90 top
SDUP5V1  TP01  [TP_040_T]  85.73 112.86 270 top
SDUP15V1  TP01  [TP_040_T]  156.86 119.76 0 top
SITE1  NPM1212-QFN28-P0.4  [SK_QFN4X4_56P_0P4MM_GRIFFI]  28.99 267.49 0 top
SITE2  NPM1212-QFN28-P0.4  [SK_QFN4X4_56P_0P4MM_GRIFFI]  28.99 207.49 0 top
SITE3  NPM1212-QFN28-P0.4  [SK_QFN4X4_56P_0P4MM_GRIFFI]  58.99 267.49 0 top
SITE4  NPM1212-QFN28-P0.4  [SK_QFN4X4_56P_0P4MM_GRIFFI]  58.99 207.49 0 top
SITE5  NPM1212-QFN28-P0.4  [SK_QFN4X4_56P_0P4MM_GRIFFI]  88.99 267.49 0 top
SITE6  NPM1212-QFN28-P0.4  [SK_QFN4X4_56P_0P4MM_GRIFFI]  88.99 207.49 0 top
SITE7  NPM1212-QFN28-P0.4  [SK_QFN4X4_56P_0P4MM_GRIFFI]  118.99 267.49 0 top
SITE8  NPM1212-QFN28-P0.4  [SK_QFN4X4_56P_0P4MM_GRIFFI]  118.99 207.49 0 top
SITE9  NPM1212-QFN28-P0.4  [SK_QFN4X4_56P_0P4MM_GRIFFI]  148.98 267.49 0 top
SITE10  NPM1212-QFN28-P0.4  [SK_QFN4X4_56P_0P4MM_GRIFFI]  148.98 207.49 0 top
SITE11  NPM1212-QFN28-P0.4  [SK_QFN4X4_56P_0P4MM_GRIFFI]  178.98 267.49 0 top
SITE12  NPM1212-QFN28-P0.4  [SK_QFN4X4_56P_0P4MM_GRIFFI]  178.98 207.49 0 top
SITE13  NPM1212-QFN28-P0.4  [SK_QFN4X4_56P_0P4MM_GRIFFI]  208.98 267.49 0 top
SITE14  NPM1212-QFN28-P0.4  [SK_QFN4X4_56P_0P4MM_GRIFFI]  208.98 207.49 0 top
SITE15  NPM1212-QFN28-P0.4  [SK_QFN4X4_56P_0P4MM_GRIFFI]  238.98 267.49 0 top
SITE16  NPM1212-QFN28-P0.4  [SK_QFN4X4_56P_0P4MM_GRIFFI]  238.98 207.49 0 top
SLOT0  DIAMONDX_SLOT0_SDU2  [PG_LTXDX_F_X1_SDU2_SL00_V3]  133.99 237.49 0 top
SLOT1  DIAMONDX_X1_DUT  [PG_LTXDX_F_X1_PG400ND_SL01_V3]  133.99 237.49 0 top
SLOT2  DIAMONDX_X1_DUT  [PG_LTXDX_F_X1_PG400ND_SL02_V3]  133.99 237.49 0 top
SLOT3  DIAMONDX_SLOT3_GX1X  [PG_LTXDX_F_X1_GX1X_SL03_V2]  133.99 237.49 0 top
SLOT4  DIAMONDX_SLOT4_GX1X  [PG_LTXDX_F_X1_GX1X_SL04]  133.99 237.49 0 top
SLOT5  DIAMONDX_X1_DUT  [PG_LTXDX_F_X1_PG400ND_SL05_V3]  133.99 237.49 0 top
SLOT6  DIAMONDX_SLOT6_PMVIX  [PG_LTXDX_F_X1_PMVIX_SL06]  133.99 237.49 0 top
SLOT7  DIAMONDX_SLOT7_PMVIX  [PG_LTXDX_F_X1_PMVIX_SL07]  133.99 237.49 0 top
SLOT8  DIAMONDX_SLOT8_PMVIX  [PG_LTXDX_F_X1_PMVIX_SL08]  133.99 237.49 0 top
SLOT9  DIAMONDX_SLOT9_PMVIX  [PG_LTXDX_F_X1_PMVIX_SL09]  133.99 237.49 0 top
SLOT10  DIAMONDX_SLOT10_HDVI  [PG_LTXDX_F_X1_HDVI_SL10_V3]  133.99 237.49 0 top
SLOT11  DIAMONDX_X1_DUT  [PG_LTXDX_F_X1_PG400ND_SL11_V3]  133.99 237.49 0 top
SLOT12  DIAMONDX_X1_DUT  [PG_LTXDX_F_X1_PG400ND_SL12_V3]  133.99 237.49 0 top
SLOT13  DIAMONDX_SLOT13_HDVI  [PG_LTXDX_F_X1_HDVI_SL13_V3]  133.99 237.49 0 top
SLOT14  DIAMONDX_X1_DUT  [PG_LTXDX_F_X1_PG400ND_SL14_V3]  133.99 237.49 0 top
SLOT15  DIAMONDX_X1_DUT  [PG_LTXDX_F_X1_PG400ND_SL15_V3]  133.99 237.49 0 top
SLOT16  DIAMONDX_X1_DUT  [PG_LTXDX_F_X1_PG400ND_SL16_V3]  133.99 237.49 0 top
SLOT17  DIAMONDX_SLOT17_GX1X  [PG_LTXDX_F_X1_GX1_SL17_V2]  133.99 237.49 0 top
SLOT18  DIAMONDX_X1_DUT  [PG_LTXDX_F_X1_PG400ND_SL18_V3]  133.99 237.49 0 top
SLOT19  DIAMONDX_SLOT19_GX1X  [PG_LTXDX_F_X1_GX1_SL19_V2]  133.99 237.49 0 top
T_+15V  TP01  [TP_040_T]  142.22 125.73 0 top
T_-15V  TP01  [TP_040_T]  47.14 115.57 0 top
T_RLY_5V  TP01  [TP_040_T]  47.14 126.11 0 top
T_USER_5V  TP01  [TP_040_T]  75.08 126.11 0 top
T_USER_12V  TP01  [TP_040_T]  112.22 125.73 0 top
T_USER_-5V  TP01  [TP_040_T]  115.7 107.98 0 top
TP_EEP_GND  TP01  [TP_040_T]  141.91 106.68 0 top
TP_EPP_SCLK  TP01  [TP_040_T]  122.15 111.51 0 top
TP_EPP_SCLK_DGND1  TP01  [TP_040_T]  141.91 110.49 0 top
TP_EPP_SDA  TP01  [TP_040_T]  122.1 107.98 0 top
TP_EPP_SDA_DGND1  TP01  [TP_040_T]  141.91 102.87 0 top
TP_EPP_VCC  TP01  [TP_040_T]  126.37 105.28 0 top
TP_EPP_VCC_DGND1  TP01  [TP_040_T]  141.91 114.3 0 top
TP_REG1_P3V3  TP01  [TP_040_T]  79.94 105.41 0 top
TP_REG1_P_5V_DGND  TP01  [TP_040_T]  177.17 101.75 0 top
TP_REG1_P_10V_DGND  TP01  [TP_040_T]  172.09 101.75 0 top
TP_SDUP5V1  TP01  [TP_040_T]  85.73 109.47 270 top
TP_SDUP15V1  TP01  [TP_040_T]  156.86 116.33 0 top
TP_USER_GND1  TP01  [TP_040_T]  63.02 111.58 90 top
TP_USER_SCLK1  TP01  [TP_040_T]  68.1 101.42 0 top
TP_USER_SCLK1_DGND1  TP01  [TP_040_T]  68.1 106.5 0 top
TP_USER_SDA1  TP01  [TP_040_T]  58.72 111.58 0 top
TP_USER_SDA1_DGND1  TP01  [TP_040_T]  68.1 111.58 0 top
U4  ADT7420UCPZ-LFCSP16  [LFCSP16_0P65MM_G]  63.02 105.23 180 top
U6  AT24C512C-SSHM-T-SOIC8  [SO8_206X127MM]  131.34 110.74 180 bottom
U44  ADP151AUJZ-0.2A-33-TSOT23-5  [TSOT23-5]  76.51 108.28 180 bottom
U46  LM1086-1.5A-A-TO263-1  [TO263_3]  171.81 115.93 180 bottom
U47  LM1086-1.5A-A-TO263-1  [TO263_3]  184.79 115.95 180 bottom
UNK0BS1  SHORT  [DEFAULT_SHORT_SMALL]  33.48 57.25 90 top
UNK0BS2  SHORT  [DEFAULT_SHORT_SMALL]  27.31 103.38 270 top
UNK1C1  1U-6.3-X7R-S6-MU  [C0603]  38.61 334.69 270 bottom
UNK1C2  2.2U-25-X8R-SA-TDK  [C1206]  29.52 237.92 90 bottom
UNK1C3  10U-6.3-X7R-S6-SS  [C0603]  27.13 238.61 270 bottom
UNK1C4  2.2U-25-X8R-SA-TDK  [C1206]  19.67 237.92 90 bottom
UNK1C5  2.2U-25-X8R-SA-TDK  [C1206]  16.47 237.92 270 bottom
UNK1C6  4.7U-6.3-X-S6  [C0603]  44.26 241.42 270 bottom
UNK1C7  0.1U-25-X7R-S6-YA  [C0603]  42.25 297.61 0 bottom
UNK1C8  1U-50-X7R-S6-TY  [C0603]  42.25 296.09 0 bottom
UNK1C9  0.1U-25-X7R-S6-YA  [C0603]  32.41 296.26 270 bottom
UNK1C12  2.2U-25-X8R-SA-TDK  [C1206]  30.99 334.29 270 bottom
UNK1CS1  CNC-S4  [C0402]  22.12 271.3 180 bottom
UNK1CS4  CNC-S4  [C0402]  22.12 267.49 0 bottom
UNK1CS5  CNC-S4  [C0402]  22.12 266.22 0 bottom
UNK1CS19  CNC-S4  [C0402]  35.85 267.02 0 bottom
UNK1CS20  CNC-S4  [C0402]  35.85 268.29 0 bottom
UNK1CS21  CNC-S4  [C0402]  35.85 269.56 0 bottom
UNK1CS22  CNC-S4  [C0402]  33.2 273.05 90 bottom
UNK1CS23  CNC-S4  [C0402]  31.93 273.05 90 bottom
UNK1CS25  CNC-S4  [C0402]  28.12 273.05 90 bottom
UNK1CS26  CNC-S4  [C0402]  26.85 273.05 270 bottom
UNK1CS27  CNC-S4  [C0402]  25.58 273.05 270 bottom
UNK1CS28  CNC-S4  [C0402]  24.31 273.05 90 bottom
UNK1K1  UA2-12NJ-V2  [RL_NECUA2_12V_V2]  33 246.27 90 bottom
UNK1K2  UA2-12NJ-V2  [RL_NECUA2_12V_V2]  25.53 246.27 90 bottom
UNK1K3  UA2-12NJ-V2  [RL_NECUA2_12V_V2]  16.66 267.46 270 bottom
UNK1K4  UA2-12NJ-V2  [RL_NECUA2_12V_V2]  33 305.28 270 bottom
UNK1K5  UA2-12NJ-V2  [RL_NECUA2_12V_V2]  40.46 305.28 270 bottom
UNK1K6  UA2-12NJ-V2  [RL_NECUA2_12V_V2]  25.53 305.68 90 bottom
UNK1K7  UA2-12NJ-V2  [RL_NECUA2_12V_V2]  18.07 305.28 270 bottom
UNK1K8  UA2-12NJ-V2  [RL_NECUA2_12V_V2]  18.07 246.27 90 bottom
UNK1K9  UA2-12NJ-V2  [RL_NECUA2_12V_V2]  18.07 332.26 90 bottom
UNK1K10  UA2-12NJ-V2  [RL_NECUA2_12V_V2]  33 288.94 90 bottom
UNK1K11  UA2-12NJ-V2  [RL_NECUA2_12V_V2]  40.46 246.27 90 bottom
UNK1K12  UA2-12NJ-V2  [RL_NECUA2_12V_V2]  40.46 288.94 90 bottom
UNK1K13  UA2-12NJ-V2  [RL_NECUA2_12V_V2]  18.07 288.54 270 bottom
UNK1K14  UA2-12NJ-V2  [RL_NECUA2_12V_V2]  25.53 288.54 270 bottom
UNK1R1  4.7K-1-S4-WA  [R0402]  16.51 261.49 180 bottom
UNK1R2  3.01K-0.1-S4-PAN  [R0402]  36.73 308.78 270 bottom
UNK1R3  10K-0.1-S4  [R0402]  29.26 301.18 270 bottom
UNK1R7  1K-1-S4  [R0402]  16.75 325.55 180 bottom
UNK1R8  1K-1-S4  [R0402]  19.39 325.55 0 bottom
UNK1R13  0-5-S4  [R0402]  36.96 476.38 0 top
UNK1R14  0-5-S4  [R0402]  39.5 476.38 0 top
UNK1R41  24K-0.1-S4  [R0402]  14.26 308.78 270 bottom
UNK1R42  44.2K-0.1-S4-PAN  [R0402]  14.26 306.58 270 bottom
UNK1RS1  0-5-S4  [R0402]  22.12 268.76 0 bottom
UNK1RS2  NC/0-5-S4  [R0402]  29.39 273.05 270 bottom
UNK1RS3  NC/0-5-S4  [R0402]  22.12 270.03 0 bottom
UNK1RS4  0-5-S4  [R0402]  30.66 273.05 270 bottom
UNK1RS5  0-5-S4  [R0402]  30.02 274.7 0 bottom
UNK1SH2  SHORT  [DEFAULT_SHORT_SMALL]  45.52 478.27 270 top
UNK1SH7  SHORT  [DEFAULT_SHORT_SMALL]  47.78 480.26 270 top
UNK1SH9  SHORT  [DEFAULT_SHORT_SMALL]  55.5 481.08 270 top
UNK1SH14  SHORT  [DEFAULT_SHORT_SMALL]  57.79 481.33 270 top
UNK1SH16  SHORT  [DEFAULT_SHORT_SMALL]  54.23 478.15 0 top
UNK1SH20  SHORT  [DEFAULT_SHORT_SMALL]  49.64 479.77 270 top
UNK1SH29  SHORT  [DEFAULT_SHORT_SMALL]  53.54 481.04 270 top
UNK1SH30  SHORT  [DEFAULT_SHORT_SMALL]  50.93 478.28 270 top
UNK1SH32  SHORT  [DEFAULT_SHORT_SMALL]  62.12 480.85 0 top
UNK1SH33  SHORT  [DEFAULT_SHORT_SMALL]  64.32 480.85 0 top
UNK1SH34  SHORT  [DEFAULT_SHORT_SMALL]  66.53 480.85 0 top
UNK1SH35  SHORT  [DEFAULT_SHORT_SMALL]  28.32 476.5 270 top
UNK1SH36  SHORT  [DEFAULT_SHORT_SMALL]  26.04 476.5 270 top
UNK1SH37  SHORT  [DEFAULT_SHORT_SMALL]  32.89 476.38 270 top
UNK1SH38  SHORT  [DEFAULT_SHORT_SMALL]  30.61 476.38 270 top
UNK1SH39  SHORT  [DEFAULT_SHORT_SMALL]  57.66 478.79 0 top
UNK1SH40  SHORT  [DEFAULT_SHORT_SMALL]  44.02 481.08 0 top
UNK1SH41  SHORT  [DEFAULT_SHORT_SMALL]  43.64 479.83 0 top
UNK1TP_AVSS2/TST  TP01  [TP_040_T]  13.84 274.45 0 top
UNK1TP_GPIO0  TP01  [TP_040_T]  16.57 295.94 90 top
UNK1TP_GPIO1  TP01  [TP_040_T]  16.57 298.48 270 top
UNK1TP_GPIO2  TP01  [TP_040_T]  29.27 295.94 0 top
UNK1TP_GPIO3  TP01  [TP_040_T]  29.27 298.48 270 top
UNK1TP_GPIO4  TP01  [TP_040_T]  26.73 295.94 270 top
UNK1TP_LED0  TP01  [TP_040_T]  24.19 298.48 270 top
UNK1TP_LED1  TP01  [TP_040_T]  24.19 295.94 90 top
UNK1TP_LED2  TP01  [TP_040_T]  26.73 298.48 270 top
UNK1TP_LSIN1_F  TP01  [TP_040_T]  30.99 330.46 0 top
UNK1TP_LSIN1_G  TP01  [TP_040_T]  28.32 478.66 0 top
UNK1TP_LSIN1_S  TP01  [TP_040_T]  28.45 330.46 0 top
UNK1TP_LSIN2/NCHGEN_F  TP01  [TP_040_T]  30.99 335.54 0 top
UNK1TP_LSIN2/NCHGEN_G  TP01  [TP_040_T]  32.89 478.54 0 top
UNK1TP_LSIN2/NCHGEN_S  TP01  [TP_040_T]  28.45 335.54 0 top
UNK1TP_LSOUT1_F  TP01  [TP_040_T]  19.67 244.47 180 top
UNK1TP_LSOUT1_G  TP01  [TP_040_T]  26.04 478.66 0 top
UNK1TP_LSOUT1_S  TP01  [TP_040_T]  21.65 298.48 270 top
UNK1TP_LSOUT2/SUSPEND1_G  TP01  [TP_040_T]  30.61 478.54 0 top
UNK1TP_LSOUT2/SUSPEND1_S  TP01  [TP_040_T]  21.65 295.94 0 top
UNK1TP_LSOUT2/SUSPEND_F  TP01  [TP_040_T]  38.86 244.47 180 top
UNK1TP_NCHG/ATB0_F  TP01  [TP_040_T]  23.93 292.54 0 top
UNK1TP_NCHG/ATB0_G  TP01  [TP_040_T]  23.93 288.14 0 top
UNK1TP_NCHG/ATB0_S  TP01  [TP_040_T]  27.13 290.34 0 top
UNK1TP_NPG/ATB1_F  TP01  [TP_040_T]  16.47 292.54 0 top
UNK1TP_NPG/ATB1_G  TP01  [TP_040_T]  16.47 288.14 0 top
UNK1TP_NPG/ATB1_S  TP01  [TP_040_T]  19.67 292.54 0 top
UNK1TP_NTC  TP01  [TP_040_T]  31.4 307.08 180 top
UNK1TP_REF_5V  TP01  [TP_040_T]  34.6 242.27 180 top
UNK1TP_SCL  TP01  [TP_040_T]  16.47 330.46 0 top
